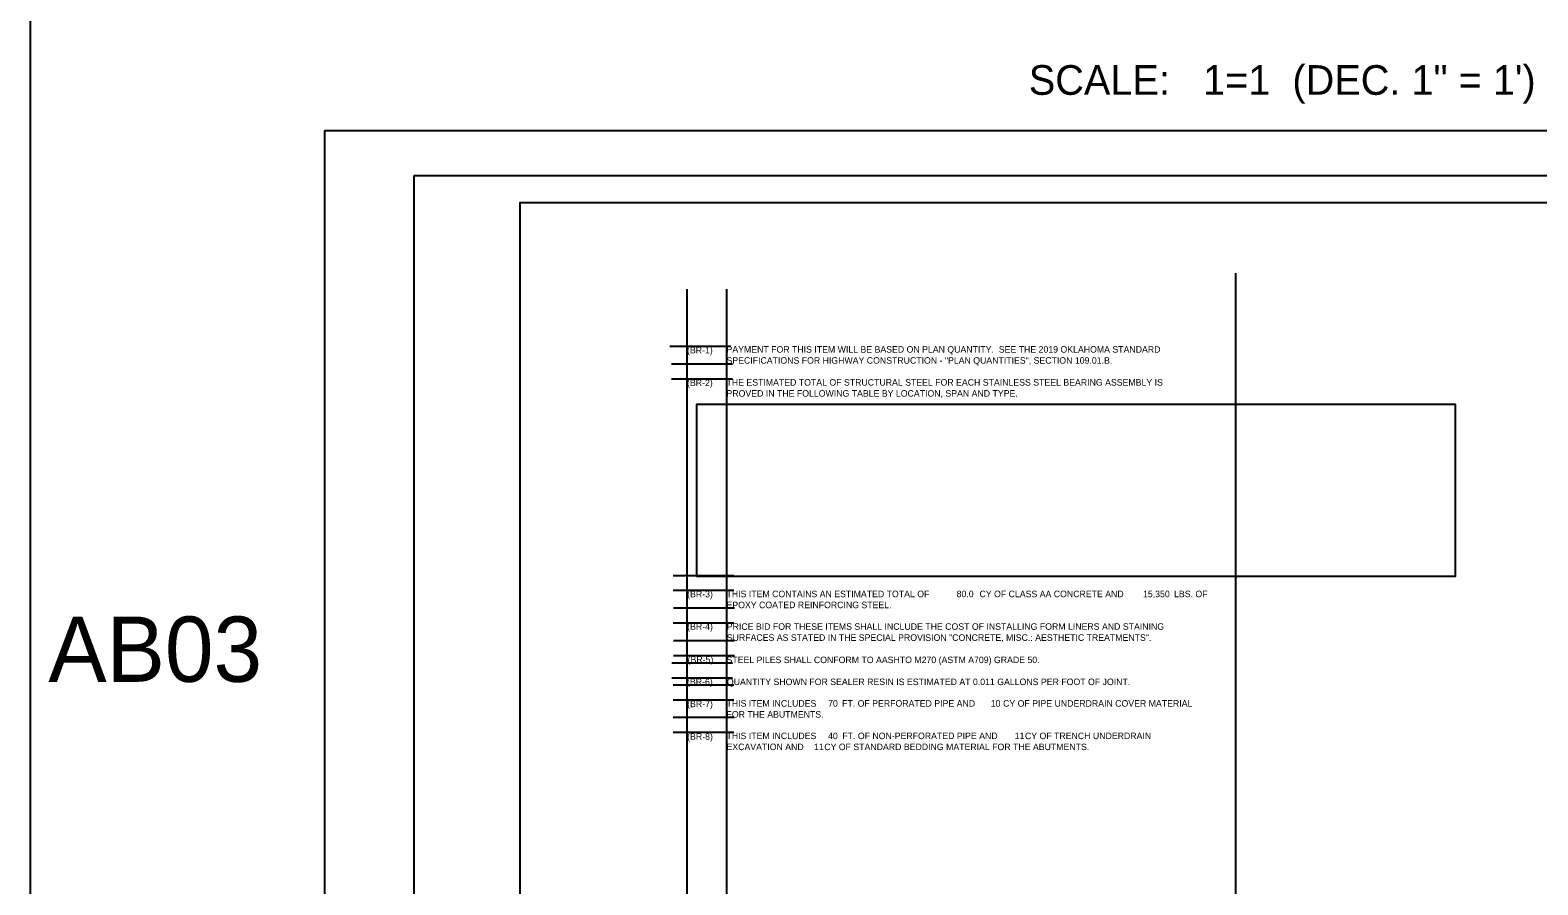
# Model space of a CAD drawing. Extents: x 12310.9 to 12354.4, y 579 to 640.5.
# Drawn here: x 12310.94 to 12338.64, y 594.74 to 610.44 of the extents above; entities that cross this region are included whole.
import ezdxf

# ---------------------------------------------------------------- set-up
doc = ezdxf.new("R2010")
doc.units = 0
for name, color, linetype in [('Default', 7, 'Continuous'), ('S', 7, 'Continuous'), ('SHT_Plot_Shape_Full', 7, 'Continuous'), ('SHT_Plot_Shape_Half', 7, 'Continuous'), ('SHT_Sheet_Border', 7, 'Continuous'), ('T', 7, 'Continuous')]:
    doc.layers.add(name, color=color, linetype=linetype)

msp = doc.modelspace()

# ---------------------------------------------------------------- linework, layer by layer
at = {"layer": 'Default'}
msp.add_lwpolyline([(12323.184, 600.41), (12337.128, 600.41), (12337.128, 603.563), (12323.184, 603.563)], close=True, dxfattribs=at)
at = {"layer": 'Defpoints'}
for p, q in [((12333.09, 587.009), (12333.09, 605.98)), ((12323.011, 586.904), (12323.011, 605.681)), ((12323.736, 605.681), (12323.736, 586.987)), ((12323.813, 604.63), (12322.697, 604.63)), ((12323.843, 604.306), (12322.727, 604.306)), ((12323.843, 604.032), (12322.727, 604.032)), ((12323.872, 600.418), (12322.757, 600.418)), ((12323.872, 600.144), (12322.757, 600.144)), ((12323.872, 600.144), (12322.757, 600.144)), ((12323.881, 599.821), (12322.765, 599.821)), ((12323.872, 599.547), (12322.757, 599.547)), ((12323.881, 599.221), (12322.765, 599.221)), ((12323.847, 598.812), (12322.731, 598.812)), ((12323.881, 598.947), (12322.765, 598.947)), ((12323.847, 598.538), (12322.731, 598.538)), ((12323.872, 598.408), (12322.756, 598.408)), ((12323.872, 598.134), (12322.756, 598.134)), ((12323.874, 597.81), (12322.758, 597.81)), ((12323.869, 597.535), (12322.753, 597.535)), ((12323.872, 597.535), (12322.756, 597.535))]:
    msp.add_line(p, q, dxfattribs=at)
at = {"layer": 'S'}
msp.add_lwpolyline([(12354.38, 640.488), (12310.944, 640.488), (12310.944, 579.031), (12354.38, 579.031)], close=True, dxfattribs=at)
at = {"layer": 'SHT_Plot_Shape_Full'}
msp.add_lwpolyline([(12316.36, 608.6), (12352.36, 608.6), (12352.36, 584.6), (12316.36, 584.6)], close=True, dxfattribs=at)
at = {"layer": 'SHT_Plot_Shape_Half'}
msp.add_lwpolyline([(12317.998, 607.775), (12351.998, 607.775), (12351.998, 585.775), (12317.998, 585.775)], close=True, dxfattribs=at)
at = {"layer": 'SHT_Sheet_Border'}
msp.add_lwpolyline([(12351.448, 586.275), (12319.948, 586.275), (12319.948, 607.275), (12351.448, 607.275)], close=True, dxfattribs=at)

# ---------------------------------------------------------------- texts
at = {"layer": 'S'}
msp.add_text('SCALE:   1=1  (DEC. 1" = 1\')', height=0.54513, dxfattribs=at).set_placement((12329.289, 609.255))
at = {"layer": 'T'}
for s, height, p in [('(BR-1)', 0.12, (12323.011, 604.502)), ('PAYMENT FOR THIS ITEM WILL BE BASED ON PLAN QUANTITY.  SEE THE 2019 OKLAHOMA STANDARD ', 0.12, (12323.736, 604.517)), ('SPECIFICATIONS FOR HIGHWAY CONSTRUCTION - "PLAN QUANTITIES", SECTION 109.01.B.', 0.12, (12323.736, 604.314)), ('(BR-2)', 0.12, (12323.011, 603.903)), ('THE ESTIMATED TOTAL OF STRUCTURAL STEEL FOR EACH STAINLESS STEEL BEARING ASSEMBLY IS ', 0.12, (12323.736, 603.911)), ('PROVED IN THE FOLLOWING TABLE BY LOCATION, SPAN AND TYPE.', 0.12, (12323.736, 603.708)), ('(BR-3)', 0.12, (12323.013, 600.021)), ('THIS ITEM CONTAINS AN ESTIMATED TOTAL OF ', 0.12, (12323.736, 600.023)), ('EPOXY COATED REINFORCING STEEL.', 0.12, (12323.736, 599.821)), ('80.0', 0.12, (12327.963, 600.023)), (' CY OF CLASS AA CONCRETE AND ', 0.12, (12328.339, 600.023)), ('15,350', 0.12, (12331.387, 600.023)), (' LBS. OF ', 0.12, (12331.913, 600.023)), ('AB03', 1.2, (12311.279, 598.468)), ('(BR-4)', 0.12, (12323.013, 599.424)), ('PRICE BID FOR THESE ITEMS SHALL INCLUDE THE COST OF INSTALLING FORM LINERS AND STAINING ', 0.12, (12323.741, 599.424)), ('SURFACES AS STATED IN THE SPECIAL PROVISION "CONCRETE, MISC.: AESTHETIC TREATMENTS".', 0.12, (12323.741, 599.221)), ('(BR-5)', 0.12, (12323.021, 598.817)), ('STEEL PILES SHALL CONFORM TO AASHTO M270 (ASTM A709) GRADE 50.', 0.12, (12323.736, 598.812)), ('(BR-6)', 0.12, (12323.011, 598.407)), ('QUANTITY SHOWN FOR SEALER RESIN IS ESTIMATED AT 0.011 GALLONS PER FOOT OF JOINT.', 0.12, (12323.743, 598.408)), ('(BR-7)', 0.12, (12323.013, 598.002)), ('THIS ITEM INCLUDES ', 0.12, (12323.736, 598.012)), ('70', 0.12, (12325.602, 598.012)), (' FT. OF PERFORATED PIPE AND ', 0.12, (12325.815, 598.012)), ('10', 0.12, (12328.59, 598.012)), (' CY OF PIPE UNDERDRAIN COVER MATERIAL ', 0.12, (12328.772, 598.012)), ('FOR THE ABUTMENTS. ', 0.12, (12323.736, 597.81)), ('(BR-8)', 0.12, (12323.013, 597.403)), ('THIS ITEM INCLUDES ', 0.12, (12323.736, 597.415)), ('40', 0.12, (12325.602, 597.415)), (' FT. OF NON-PERFORATED PIPE AND ', 0.12, (12325.819, 597.415)), ('11', 0.12, (12329.03, 597.415)), (' CY OF TRENCH UNDERDRAIN ', 0.12, (12329.174, 597.415)), ('EXCAVATION AND ', 0.12, (12323.736, 597.213)), ('11', 0.12, (12325.343, 597.213)), (' CY OF STANDARD BEDDING MATERIAL FOR THE ABUTMENTS.  ', 0.12, (12325.487, 597.213))]:
    msp.add_text(s, height=height, dxfattribs=at).set_placement(p)

doc.saveas('drawing.dxf')
